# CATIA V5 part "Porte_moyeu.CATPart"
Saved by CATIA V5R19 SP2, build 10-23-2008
Part number: Porte_moyeu
Bounding box of the stored display mesh (mm): x -130 to 151.835, y -810 to -759.167, z -151 to 152.5
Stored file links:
  G:\EU_thinkMotion\CFAO_2010\MMS_groupe3\MMS_groupe3\pmayet\pmayet_assemblage_animation\pmayet_assemblage_animation\Porte_moyeu.CATPart
  G:\EU_thinkMotion\CFAO_2010\MMS_groupe3\MMS_groupe3\pmayet\pmayet_assemblage_animation\pmayet_assemblage_animation\pmayet_assemblage_animation.CATProduct
  G:\EU_thinkMotion\CFAO_2010\MMS_groupe3\MMS_groupe3\pmayet\pmayet_assemblage_animation\pmayet_assemblage_animation\Squelette_porte_moyeu.CATPart
  G:\EU_thinkMotion\CFAO_2010\MMS_groupe3\MMS_groupe3\pmayet\pmayet_assemblage_animation\pmayet_assemblage_animation\Squelette_barre_bas.CATPart
  C:\Users\Pauline\Desktop\Projet Catia\Assemblage\Part1.CATPart
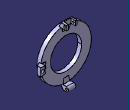
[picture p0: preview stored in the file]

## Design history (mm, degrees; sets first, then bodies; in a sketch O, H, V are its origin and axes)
Parameters
  Rayon_porte_moyeu = 80 mm
  `Epaisseur_porte-moyeu` = 10 mm
  Distance_entre_rayons = 50 mm
  Rayon_trou = 5 mm
  Angle_Patte_bas = 7 deg
  Angle_Patte_haut = 10 deg
  `Longueur=Angle_Patte_haut` = 10
  `Longueur=Angle_Patte_bas` = 7
  `Rayon_sphère_biellette` = 8 mm
  `Angle_Patte_coté` = 8 deg
Set1
  Plane1: linked copy from another document
  Point1: linked copy from another document
  Plane2 to Plane4: linked copy from another document
  Point2: linked copy from another document
  Line1: linked copy from another document
  Plane5 to Plane7: linked copy from another document
  Point3: linked copy from another document
  Point4: linked copy from another document
  Plane8 to Plane13: linked copy from another document
Body1 (main body)
  Sketch1 on Plane1, origin (0, -800, 0), H (-1, 0, 0), V (0, 0, 1)
    circle A1 centre (0, 0) radius 80
    reference projected point E1 (0, 0) from Point1
    reference projected point E2 (0, 0) from Point1
    circle A2 centre (0, 0) radius 130
    point P2 (0, 0)
    reference projected point E3 (0, 0) from Point1
    distance E2 A1 = 80 {= Rayon_porte_moyeu}
    distance P2 A2 = 130 {= Rayon_porte_moyeu +Distance_entre_rayons}
    concentricity: A1 E1, A2 E3
  Pad1: profile Sketch1, direction (0, 1, 0), length 10 {= `Epaisseur_porte-moyeu`}, mirrored extent
  Sketch2 on Plane2, origin (0, 0, 0), H (0, 1, 0), V (0, 0, 1)
    line L1 (-800, -130) -> (-787.5, -150)
    point P1 (-800, -130)
    point P2 (-787.5, -150)
    reference intersected line E1 through (-800, 0) direction (0, 1) from Plane1
    reference projected point E2 (-800, 0) from Point1
    reference intersected line E3 through (0, -140) direction (-1, 0) from Plane4
    line L2 (-790, -105) -> (-787.5, -130)
    point P3 (-790, -105)
    point P4 (-787.5, -130)
    reference projected line E4 (-800, 0) -> (-770, 0) from Line1
    reference intersected line E5 through (-800, 0) direction (0, 1) from Plane1
    reference intersected line E6 through (0, -140) direction (-1, 0) from Plane4
    reference intersected line E7 through (-770, 0) direction (0, 1) from Plane5
    line L3 (-787.5, -130) -> (-770, -130)
    line L4 (-770, -150) -> (-787.5, -150)
    point P6 (-770, -130)
    point P7 (-770, -150)
    reference projected point E8 (-770, -140) from Point2
    reference projected point E9 (-770, -140) from Point2
    reference intersected line E10 through (-770, 0) direction (0, 1) from Plane5
    arc A1 centre (-770, -140) radius 10 from (-770, -150) to (-770, -130) ccw
    point P9 (-770, -140)
    point P10 (-770, -150)
    point P11 (-770, -130)
    reference projected point E11 (-770, -140) from Point2
    distance P1 E1 = 0
    distance E2 P1 = 130 {= Rayon_porte_moyeu + Distance_entre_rayons}
    distance P2 E3 = 10 {= Rayon_trou *2}
    distance E4 P3 = 105 {= Rayon_porte_moyeu + Distance_entre_rayons /2}
    distance E5 P3 = 10 {= `Epaisseur_porte-moyeu`}
    distance E6 P4 = 10 {= Rayon_trou * 2}
    distance E7 P4 = 17.5 {= Rayon_trou *3.5}
    distance E8 L4 = 10 {= Rayon_trou *2}
    distance E9 L3 = 10 {= Rayon_trou *2}
    distance P2 E10 = 17.5 {= Rayon_trou *3.5}
    length L3 = 17.5 {= Rayon_trou *3.5}
    length L4 = 17.5 {= Rayon_trou *3.5}
    radius A1 = 10 {= Rayon_trou *2}
    distance P10 P7 = 0
    distance P11 P6 = 0
    horizontal: L3 H, L4 H
    coincidence: E11 P9
  Shaft1: profile Sketch2, axis Line1, angle 7 {= Angle_Patte_bas}, second angle 7 {= Angle_Patte_bas}
  Sketch3 on Plane2, origin (0, 0, 0), H (0, 1, 0), V (0, 0, 1)
    line L1 (-787.5, 152.5) -> (-760, 152.5)
    line L2 (-760, 152.5) -> (-760, 130)
    line L3 (-760, 130) -> (-787.5, 130)
    line L4 (-800, 130) -> (-787.5, 152.5)
    point P5 (-787.5, 152.5)
    point P6 (-800, 130)
    line L5 (-790, 105) -> (-787.5, 130)
    point P7 (-790, 105)
    point P8 (-787.5, 130)
    reference projected point E1 (-800, 0) from Point1
    reference intersected line E2 through (-800, 0) direction (0, 1) from Plane1
    reference intersected line E3 through (0, 140) direction (-1, 0) from Plane6
    reference intersected line E4 through (-770, 0) direction (0, 1) from Plane7
    reference intersected line E5 through (-770, 0) direction (0, 1) from Plane7
    reference intersected line E6 through (0, 0) direction (-1, 0) from Plane3
    reference intersected line E7 through (0, 140) direction (-1, 0) from Plane6
    reference intersected line E8 through (-800, 0) direction (0, 1) from Plane1
    reference projected point E9 (-770, 140) from Point3
    reference projected point E10 (-770, 140) from Point3
    distance E1 P6 = 130 {= Rayon_porte_moyeu + Distance_entre_rayons}
    distance E2 P6 = 0
    distance E3 P5 = 12.5 {= Rayon_trou *2.5}
    distance E4 P5 = 17.5 {= Rayon_trou *3.5}
    distance E5 P8 = 17.5 {= Rayon_trou *3.5}
    distance E6 P7 = 105 {= Rayon_porte_moyeu + Distance_entre_rayons /2}
    distance E7 P8 = 10 {= Rayon_trou *2}
    distance E8 P7 = 10 {= `Epaisseur_porte-moyeu`}
    distance E9 L3 = 10 {= Rayon_trou *2}
    distance E10 L2 = 10 {= Rayon_trou *2}
    length L1 = 27.5 {= Rayon_trou *5.5}
    length L3 = 27.5 {= Rayon_trou *5.5}
    horizontal: L1 H, L3 H
    vertical: L2 V
    coincidence: P5 L1
  Shaft2: profile Sketch3, axis Line1, angle 10 {= Angle_Patte_haut}, second angle 10 {= Angle_Patte_haut}
  Sketch4 on Plane3, origin (0, 0, 0), H (1, 0, 0), V (0, 1, 0)
    line L1 (130, -800) -> (152, -786)
    point P1 (130, -800)
    point P2 (152, -786)
    reference intersected line E1 through (0, 0) direction (0, 1) from Plane2
    reference intersected line E2 through (0, -800) direction (-1, 0) from Plane1
    line L2 (105, -790) -> (128, -786)
    point P3 (105, -790)
    point P4 (128, -786)
    reference intersected line E3 through (0, -800) direction (-1, 0) from Plane1
    reference intersected line E4 through (0, 0) direction (0, 1) from Plane2
    line L3 (128, -770) -> (152, -770)
    line L4 (152, -770) -> (152, -786)
    line L5 (128, -786) -> (128, -770)
    point P7 (152, -786)
    point P8 (128, -786)
    reference projected point E5 (140, -770) from Point4
    reference projected point E6 (140, -770) from Point4
    reference projected point E7 (140, -770) from Point4
    reference intersected line E8 through (140, 0) direction (0, 1) from Plane8
    reference intersected line E9 through (140, 0) direction (0, 1) from Plane8
    distance P1 E1 = 130 {= Rayon_porte_moyeu +Distance_entre_rayons}
    distance E2 P1 = 0
    distance E3 P3 = 10 {= `Epaisseur_porte-moyeu`}
    distance E4 P3 = 105 {= Rayon_porte_moyeu +Distance_entre_rayons /2}
    distance E5 L3 = 0
    distance E6 L5 = 12 {= `Rayon_sphère_biellette` *1.5}
    distance E7 L4 = 12 {= `Rayon_sphère_biellette` *1.5}
    length L4 = 16 {= `Rayon_sphère_biellette` *2}
    length L5 = 16 {= `Rayon_sphère_biellette` *2}
    distance E8 P2 = 12 {= `Rayon_sphère_biellette` *1.5}
    distance P2 P7 = 0
    distance E9 P4 = 12 {= `Rayon_sphère_biellette` *1.5}
    distance P8 P4 = 0
    horizontal: L3 H
    vertical: L4 V, L5 V
  Shaft3: profile Sketch4, axis Line1, angle 8 {= `Angle_Patte_coté`}, second angle 8 {= `Angle_Patte_coté`}
  Sketch5 on Plane8, origin (140, 0, 0), H (0, 1, 0), V (0, 0, 1)
    arc A1 centre (-770, 0) radius 8 from (-770, 8) to (-770, -8) ccw
    point P1 (-770, 0)
    point P2 (-770, 8)
    point P3 (-770, -8)
    reference projected point E1 (-770, 0) from Point4
    reference intersected line E2 through (-770, 0) direction (0, 1) from Plane9
    reference intersected line E3 through (-770, 0) direction (0, 1) from Plane9
    line L1 (-770, 8) -> (-770, -8)
    point P4 (-770, 8)
    point P5 (-770, -8)
    reference projected line E4 (-770, 21.1543) -> (-770, -21.1543) from edge [face of Shaft3 from Sketch4.L4 | face of Shaft3 from Sketch4.L3]
    radius A1 = 8 {= `Rayon_sphère_biellette`}
    distance E2 P2 = 0
    distance P3 E3 = 0
    distance E4 L1 = 0
    distance P2 P4 = 0
    distance P3 P5 = 0
    coincidence: P1 E1
  Sketch6 on Plane10, origin (0, 0, 0), H (1, 0, 0), V (0, 1, 0)
    arc A1 centre (140, -770) radius 8 from (132, -770) to (148, -770) ccw
    point P1 (140, -770)
    point P2 (132, -770)
    point P3 (148, -770)
    reference projected point E1 (140, -770) from Point4
    reference intersected line E2 through (0, -770) direction (-1, 0) from Plane9
    reference intersected line E3 through (0, -770) direction (-1, 0) from Plane9
    radius A1 = 8 {= `Rayon_sphère_biellette`}
    distance P2 E2 = 0
    distance E3 P3 = 0
    coincidence: E1 P1
  Slot1: profile Sketch5, centre curve Sketch6
  Sketch7 on Plane2, origin (0, 0, 0), H (0, 1, 0), V (0, 0, 1)
    line L1 (-787.5, 150.1832) -> (-760, 150.1832)
    line L2 (-760, 150.1832) -> (-760, 128.025)
    line L3 (-760, 128.025) -> (-800, 128.025)
    point P4 (-800, 128.025)
    reference projected line E1 (-760, 150.1832) -> (-787.5, 150.1832) from edge [face of Shaft2 from Sketch3.L1 | face of Shaft2]
    reference projected line E2 (-760, 150.1832) -> (-787.5, 150.1832) from edge [face of Shaft2 from Sketch3.L1 | face of Shaft2]
    reference projected line E3 (-787.5, 128.025) -> (-760, 128.025) from edge [face of Shaft2 from Sketch3.L3 | face of Shaft2]
    reference projected line E4 (-787.5, 128.025) -> (-760, 128.025) from edge [face of Shaft2 from Sketch3.L3 | face of Shaft2]
    reference projected line E5 (-760, 128.025) -> (-760, 150.1832) from edge [face of Shaft2 from Sketch3.L2 | face of Shaft2]
    reference projected line E6 (-760, 128.025) -> (-760, 150.1832) from edge [face of Shaft2 from Sketch3.L2 | face of Shaft2]
    line L4 (-787.5252, 150.1385) -> (-800, 128.025)
    point P6 (-800, 128.025)
    reference projected line E7 (-787.5, 150.1832) -> (-800.8513, 126.5159) from edge [face of Shaft2 from Sketch3.L4 | face of Shaft2]
    reference projected line E8 (-787.5, 150.1832) -> (-800.8513, 126.5159) from edge [face of Shaft2 from Sketch3.L4 | face of Shaft2]
    distance L1 E2 = 0
    distance L3 E4 = 0
    distance E5 L2 = 0
    length L1 = 27.5 {= Rayon_trou *5.5}
    distance E7 L4 = 0
    distance P6 L3 = 0
    distance P6 P4 = 0
    horizontal: L1 H, L3 H
    vertical: L2 V
    parallelism: L1 E1, L3 E3, E6 L2, E8 L4
  Pad2: profile Sketch7, direction (1, 0, 0), length 27.0389 {= (Rayon_porte_moyeu + Distance_entre_rayons + Rayon_trou *5 )*`Longueur=Angle_Patte_haut` *3.14/180}, mirrored extent
  Sketch8 on Plane6, origin (0, 0, 140), H (1, 0, 0), V (0, 1, 0)
    line L1 (-17.6778, -760) -> (17.6778, -760)
    line L2 (17.6778, -760) -> (17.6778, -782.5)
    line L3 (17.6778, -782.5) -> (-17.6778, -782.5)
    line L4 (-17.6778, -782.5) -> (-17.6778, -760)
    reference projected line E1 (-26.0472, -760) -> (26.0472, -760) from edge [face of Shaft2 from Sketch3.L1 | face of Shaft2 from Sketch3.L2]
    reference projected point E2 (0, -770) from Point3
    reference projected point E3 (0, -770) from Point3
    reference projected point E4 (0, -770) from Point3
    distance E1 L1 = 0
    distance E2 L3 = 12.5 {= Rayon_trou *2.5}
    distance E3 L4 = 17.6778 {= (Rayon_porte_moyeu + Distance_entre_rayons ) * `Longueur=Angle_Patte_haut` *3.14/180-5mm}
    distance E4 L2 = 17.6778 {= (Rayon_porte_moyeu + Distance_entre_rayons ) * `Longueur=Angle_Patte_haut` *3.14/180-5mm}
    horizontal: L1 H, L3 H
    vertical: L2 V, L4 V
  Pocket1: profile Sketch8, direction (0, 0, -1), length 15, mirrored extent
  Sketch9 on Plane2, origin (0, 0, 0), H (0, 1, 0), V (0, 0, 1)
    circle A1 centre (-770, 140) radius 5
    point P1 (-770, 140)
    reference projected point E1 (-770, 140) from Point3
    distance P1 A1 = 5 {= Rayon_trou}
    coincidence: P1 E1
  Pocket2: profile Sketch9, direction (-1, 0, 0), up to end face of Pad2, opposite side up to start face of Pad2
  Sketch10 on Plane2, origin (0, 0, 0), H (0, 1, 0), V (0, 0, 1)
    line L1 (-787, -151) -> (-770, -151)
    point P1 (-787, -151)
    point P2 (-770, -151)
    reference intersected line E1 through (0, -140) direction (-1, 0) from Plane4
    reference intersected line E2 through (0, -140) direction (-1, 0) from Plane4
    reference intersected line E3 through (-770, 0) direction (0, 1) from Plane5
    line L2 (-800.8533, -129) -> (-770, -129)
    point P3 (-800.8533, -129)
    point P4 (-770, -129)
    reference intersected line E4 through (0, -140) direction (-1, 0) from Plane4
    reference intersected line E5 through (0, -140) direction (-1, 0) from Plane4
    reference intersected line E6 through (-770, 0) direction (0, 1) from Plane5
    line L3 (-800.8533, -129) -> (-787, -151)
    point P5 (-800.8533, -129)
    point P6 (-787, -151)
    arc A1 centre (-770, -140) radius 11 from (-770, -151) to (-770, -129) ccw
    point P7 (-770, -140)
    point P8 (-770, -151)
    point P9 (-770, -129)
    reference projected point E7 (-770, -140) from Point2
    reference projected line E8 (-800.9069, -127.5907) -> (-787.5, -148.8819) from edge [face of Shaft1 from Sketch2.L1 | face of Shaft1]
    distance E1 L1 = 11 {= Rayon_trou *2.2}
    distance P2 E3 = 0
    distance E4 L2 = 11 {= Rayon_trou *2.2}
    distance P4 E6 = 0
    distance P5 L2 = 0
    distance P5 P3 = 0
    distance P6 L1 = 0
    distance P6 P1 = 0
    length L1 = 17 {= Rayon_trou *3.4}
    radius A1 = 11 {= Rayon_trou *2.2}
    distance P2 P8 = 0
    distance P4 P9 = 0
    parallelism: E2 L1, E5 L2, L3 E8
    coincidence: E7 P7
  Pad3: profile Sketch10, direction (1, 0, 0), length 18.5609 {= (Rayon_porte_moyeu + Distance_entre_rayons  + Rayon_trou *4.4) *`Longueur=Angle_Patte_bas` *3.14/180}, mirrored extent
  Sketch11 on Plane2, origin (0, 0, 0), H (0, 1, 0), V (0, 0, 1)
    circle A1 centre (-770, -140) radius 5
    point P1 (-770, -140)
    reference projected point E1 (-770, -140) from Point2
    distance P1 A1 = 5 {= Rayon_trou}
    coincidence: E1 P1
  Pocket3: profile Sketch11, direction (-1, 0, 0), up to end face of Pad3, opposite side up to start face of Pad3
